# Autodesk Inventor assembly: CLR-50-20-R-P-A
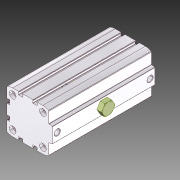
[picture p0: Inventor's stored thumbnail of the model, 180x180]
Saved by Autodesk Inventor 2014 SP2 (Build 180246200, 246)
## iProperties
Shininess: 64.0
Length Units: 11269
Angle Units: 11279
Time Units: 11290
Mass Units: 11283
Length Display Precision: 3
Angle Display Precision: 2
Compacted: True
Created: 2004-03
Part Number: CLR-50-20-R-P-A
Document SubType Name: Assembly
Cost Center: 0,6 kg
Designer: Peter Kastler
Manufacturer: Standard
Standards Organization: Custom
Description: Schwenkspanner
Vendor: Festo
Mass: 583.576 g
Surface Area: 1279 cm^2
Volume: 583.576 cm^3
Density: 1 g/cm^3
Density: 0.0
Volumn: 0.0
Area: 0.0
PropertySet Name: Model Information
Control State: 0
Master: False
Checked Out: False
TotalMass: 0,6 kg
Cideon_Mass: 0.58
Cideon_Mass_Unit: kg
Cideon_Area: 0,128 m^2
Cideon_User: konstruktion
Cideon_SaveDate: 10.10.2018
Cideon_SaveTime: 09:11:57
Author: Peter Kastler
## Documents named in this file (4)
- C:\Arbeitsbereich\Workspace\SP\Schwenkspanner\CLR-50-20-R-P-A.iam
- C:\Arbeitsbereich\Workspace\SP\Schwenkspanner\CLR-50-20-R-P-A_1.ipt
- C:\Arbeitsbereich\Workspace\SP\Schwenkspanner\CLR-50-20-R-P-A_2.ipt
- C:\Arbeitsbereich\Workspace\SP\Schwenkspanner\CLR-50-20-R-P-A_3.ipt
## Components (3 placed, 3 different names)
1. CLR-50-20-R-P-A_1:1 — Einfügen:1, HUB, Passend:2, Drehwinkel
2. CLR-50-20-R-P-A_2:1 — HUB, Passend:2, Drehwinkel
3. CLR-50-20-R-P-A_3:1 — Einfügen:1
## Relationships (4: Mate 2, Insert 1, Angle 1)
- Einfügen:1 [Insert]: CLR-50-20-R-P-A_1:1 ↔ CLR-50-20-R-P-A_3:1
- HUB [Mate]: CLR-50-20-R-P-A_1:1 ↔ CLR-50-20-R-P-A_2:1
- Passend:2 [Mate]: CLR-50-20-R-P-A_1:1 ↔ CLR-50-20-R-P-A_2:1
- Drehwinkel [Angle]: CLR-50-20-R-P-A_1:1 ↔ CLR-50-20-R-P-A_2:1
## Named parameters: Drehung = 0
